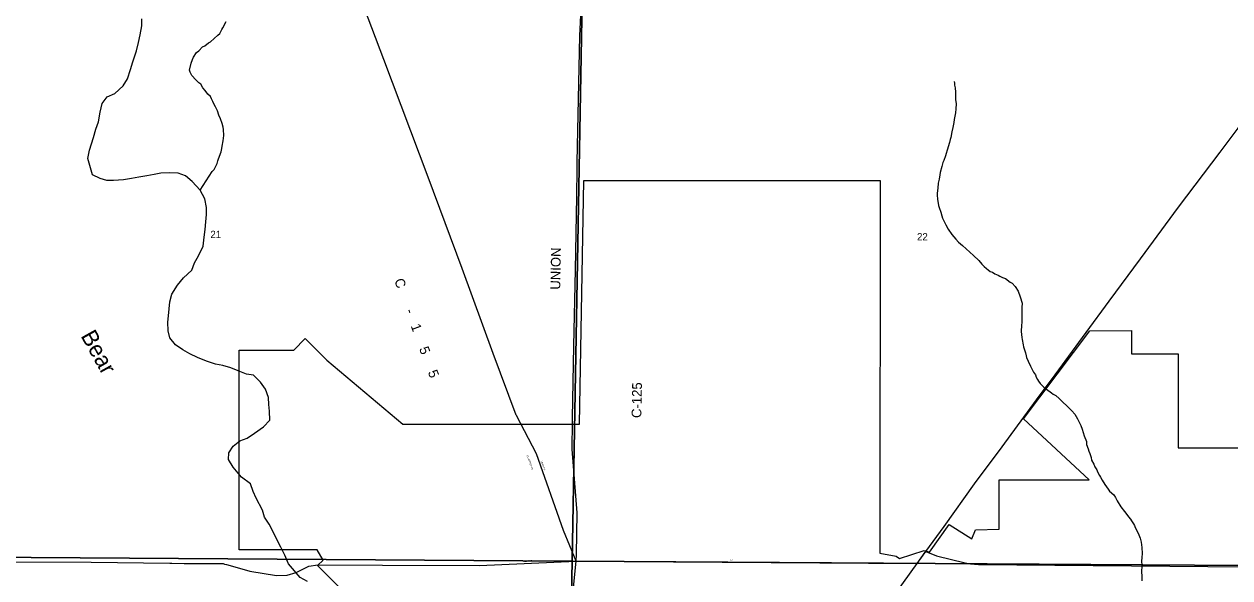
# Model space of a CAD drawing. Extents: x 1312308 to 1684953, y 460642 to 865172.
# Drawn here: x 1455224 to 1464469, y 619650 to 623895 of the extents above; entities that cross this region are included whole.
import ezdxf

# ---------------------------------------------------------------- set-up
doc = ezdxf.new("R2010")
doc.units = 0
for name, color, linetype in [('GM_X_City_Street', 7, 'Continuous'), ('GM_X_City_Street_Text', 7, 'Continuous'), ('GM_X_Corporation', 7, 'Continuous'), ('GM_X_County_Road', 7, 'Continuous'), ('GM_X_County_Road_Text', 7, 'Continuous'), ('GM_X_Minor_River', 7, 'Continuous'), ('GM_X_Minor_River_Text', 7, 'Continuous'), ('GM_X_Section', 7, 'Continuous'), ('GM_X_Section_Text', 7, 'Continuous'), ('GM_X_State_Route', 7, 'Continuous'), ('GM_X_Township_Road', 7, 'Continuous')]:
    doc.layers.add(name, color=color, linetype=linetype)

msp = doc.modelspace()

# ---------------------------------------------------------------- linework, layer by layer
at = {"layer": 'GM_X_City_Street'}
for points in [[(1459457.4, 619777.4), (1459360.2, 620012.5), (1459153.3, 620600.1), (1458999, 620894), (1458997.4, 620898.3)], [(1459458.5, 619829.7), (1459465.2, 620148.8), (1459425.5, 620637.7), (1459429.1, 620847.6), (1459429.6, 620874.9)], [(1456928.7, 619709.6), (1456954.5, 619702.5), (1457158, 619668), (1457240.2, 619672.2), (1457310.8, 619690.7), (1457406, 619738.8), (1457476.4, 619751.3), (1457971.1, 619748.5), (1458714.2, 619746.3), (1459457.4, 619777.4), (1462070.7, 619760.9), (1462136.9, 619851.6), (1462218.3, 619819.8), (1462438.1, 619764.9), (1462481.1, 619757.8), (1462540.7, 619752.3), (1464594.2, 619735.8), (1465504.2, 619732.6), (1466316.9, 619702.8), (1467220.2, 619701.2), (1467975.3, 619702.8)], [(1459363.6, 616687.1), (1459353.3, 616750.7), (1459368.2, 617583), (1459378.8, 618140.6), (1459394.2, 618728.2), (1459401.2, 619217.6), (1459457.4, 619777.4), (1459458.5, 619829.7)], [(1456776.4, 619751.7), (1456928.7, 619709.6)]]:
    msp.add_lwpolyline(points, dxfattribs=at)
at = {"layer": 'GM_X_Corporation'}
msp.add_lwpolyline([(1457716.9, 619501.9), (1457474.3, 619744.7), (1457516.8, 619787.1), (1457471.8, 619865.1), (1456871.8, 619865.2), (1456871.9, 621396.3), (1457290.9, 621396.3), (1457379.3, 621484.7), (1457544, 621319.9), (1458128.5, 620829), (1459482.6, 620828.9), (1459516, 622695.8), (1461786.3, 622695.5), (1461786.2, 619838.6), (1461910.6, 619816.6), (1461935.2, 619799.4), (1462123.8, 619859.7), (1462164.9, 619847.3), (1462315.8, 620058.7), (1462491.3, 619949), (1462519.5, 620019.5), (1462700.8, 620023.4), (1462700.8, 620400.7), (1463390.8, 620400.7), (1462886.2, 620869.4), (1463395.2, 621544.4), (1463713.6, 621547.1), (1463713.6, 621367), (1464073.6, 621367), (1464073.5, 620646.4), (1464703.5, 620646.5)], dxfattribs=at)
at = {"layer": 'GM_X_County_Road'}
for points in [[(1458997.4, 620898.3), (1458819.1, 621371.3), (1458583.5, 622020.5), (1458321, 622722.5), (1457980.8, 623622.7), (1457769.3, 624187), (1457623.6, 624565.4), (1457501.7, 624754.6), (1457352.5, 624890.3), (1457210.6, 624993.7), (1457105.9, 625064), (1457115.4, 625863), (1457105.7, 625964.9), (1457061.5, 626103.5), (1456978.7, 626269), (1456791.8, 626665.5), (1456559.2, 627244.6), (1456374.5, 627669.9), (1456047.3, 628401.2), (1455783.7, 628992)], [(1459463.9, 622759.1), (1459465.3, 622835.9), (1459485.3, 623806.4), (1459520.8, 624537.8), (1459507, 624939.2), (1459508.2, 625062.6)], [(1459461.1, 622602.1), (1459463.9, 622759.1)], [(1459429.6, 620874.9), (1459439.4, 621430), (1459450.6, 622011.6), (1459460.6, 622573.4), (1459461.1, 622602.1)]]:
    msp.add_lwpolyline(points, dxfattribs=at)
at = {"layer": 'GM_X_Minor_River'}
for points in [[(1456622.3, 621311.7), (1456552.7, 621339.8), (1456495.2, 621367.5), (1456441.8, 621399.1), (1456384.5, 621436.9), (1456339.8, 621490.4), (1456329.2, 621545), (1456324.9, 621609.4), (1456330.3, 621659.4), (1456335.8, 621713.5), (1456341.2, 621765.6), (1456356.9, 621825.4), (1456399, 621894.5), (1456446.8, 621949.4), (1456508.6, 622008), (1456530.3, 622065.6), (1456561.9, 622118.9), (1456596.1, 622192.3), (1456604, 622262.4), (1456611.6, 622320.4), (1456617.3, 622380.5), (1456620.8, 622436.7), (1456622.3, 622488.9), (1456610, 622555.5), (1456573.6, 622622.8), (1456513.2, 622688.8), (1456462.1, 622732.4), (1456404.3, 622752.2), (1456336.1, 622754.1), (1456271.7, 622751.9), (1456221.2, 622743.3), (1456164.6, 622730.8), (1456102.1, 622722.5), (1456047.5, 622712), (1455984.9, 622701.7), (1455908.4, 622695.9), (1455858.2, 622695.3), (1455806.3, 622710.8), (1455746.8, 622738.6), (1455726.7, 622811.5), (1455712, 622864.1), (1455725.9, 622930), (1455754.6, 623025.6), (1455772.4, 623089.4), (1455794.1, 623147), (1455806.1, 623219), (1455822, 623286.8), (1455859.6, 623338), (1455918.6, 623362.4), (1455982.5, 623422.9), (1456016.1, 623476.2), (1456038.2, 623547.9), (1456057.8, 623605.6), (1456084.3, 623691.2), (1456100.1, 623755), (1456113.7, 623812.9), (1456125.7, 623882.8), (1456127.1, 623935)], [(1456573.6, 622622.8), (1456665.5, 622766), (1456680, 622779.7), (1456703.3, 622825.4), (1456709.9, 622847.4), (1456714.3, 622863.4), (1456733.8, 622915.2), (1456740.5, 622941.2), (1456743, 622959.3), (1456750.1, 622999.3), (1456755.2, 623041.5), (1456752.3, 623087.8), (1456748.7, 623104), (1456743.4, 623132.3), (1456728.3, 623168.9), (1456716.9, 623197.3), (1456705.7, 623229.8), (1456690.4, 623260.3), (1456678.9, 623284.8), (1456671.4, 623303), (1456659.8, 623323.4), (1456652.2, 623339.7), (1456632.5, 623358.3), (1456611.1, 623387), (1456593.5, 623407.5), (1456578.1, 623434.1), (1456562.3, 623444.5), (1456540.7, 623467.2), (1456509.4, 623502.2), (1456496, 623526.6), (1456492.3, 623540.8), (1456503.8, 623594.8), (1456514.6, 623622.7), (1456523.1, 623640.6), (1456546.2, 623678.3), (1456562.6, 623690), (1456591.6, 623721.4), (1456609.9, 623729), (1456636.6, 623750.5), (1456652.9, 623758.2), (1456708.6, 623811.1), (1456723, 623822.8), (1456739.9, 623852.6), (1456748.3, 623866.5), (1456771.7, 623916.2)], [(1462355.5, 623456.3), (1462357.1, 623442.2), (1462356.7, 623426.1), (1462362.2, 623405.8), (1462365.4, 623373.6), (1462364.9, 623355.5), (1462366.3, 623331.3), (1462366, 623317.2), (1462369.1, 623282.9), (1462368.2, 623246.8), (1462365.3, 623214.6), (1462354, 623164.6), (1462351.3, 623140.5), (1462344.3, 623102.5), (1462337.4, 623070.5), (1462328.2, 623026.4), (1462323.8, 623010.4), (1462319.2, 622986.4), (1462301.6, 622928.5), (1462292.8, 622902.6), (1462288.4, 622886.6), (1462275.4, 622848.7), (1462269, 622834.7), (1462260.1, 622804.8), (1462246.9, 622758.8), (1462244.4, 622740.8), (1462239.5, 622706.7), (1462232.6, 622674.7), (1462229.7, 622638.5), (1462224.6, 622598.4), (1462224.2, 622584.3), (1462227.4, 622552.1), (1462234.3, 622505.6), (1462239.9, 622489.4), (1462253, 622452.9), (1462260.4, 622426.5), (1462266, 622408.3), (1462283.1, 622371.7), (1462290.8, 622357.4), (1462308, 622322.8), (1462337.2, 622281.8), (1462368.5, 622246.8), (1462388, 622224.2), (1462419.5, 622197.3), (1462447.1, 622172.5), (1462474.6, 622147.7), (1462504.1, 622120.8), (1462543.4, 622083.7), (1462566.8, 622054.9), (1462584.4, 622036.4), (1462602.2, 622021.9), (1462616, 622011.5), (1462631.8, 621999), (1462649.7, 621992.5), (1462667.6, 621982.1), (1462691.5, 621971.4), (1462705.3, 621963), (1462725.2, 621952.5), (1462749.1, 621943.9), (1462784.6, 621916.8), (1462798.5, 621908.5), (1462822, 621883.8), (1462845.3, 621849), (1462862.2, 621804.3), (1462875.1, 621755.7), (1462874.2, 621723.5), (1462875, 621675.2), (1462873.3, 621608.9), (1462870.7, 621586.8), (1462869.5, 621538.5), (1462874.3, 621492.1), (1462875.9, 621478), (1462882.9, 621435.6), (1462886.6, 621421.4), (1462901.5, 621374.8), (1462906.9, 621352.5), (1462910.6, 621338.3), (1462922, 621311.9), (1462939.1, 621273.2), (1462962, 621226.4), (1462977.6, 621205.9), (1462983.2, 621187.7), (1462994.8, 621171.3), (1463002.5, 621157), (1463014.2, 621140.6), (1463043.6, 621111.7), (1463063.4, 621097.2), (1463100.8, 621068.1), (1463114.7, 621059.7), (1463134.5, 621047.2), (1463160.1, 621024.4), (1463191.5, 620993.5), (1463217.1, 620972.7), (1463258.3, 620929.5), (1463279.8, 620904.8), (1463301, 620870.1), (1463318.2, 620833.4), (1463325.9, 620819.2), (1463337.2, 620790.7), (1463352, 620738), (1463369, 620695.3)], [(1457396.1, 619622.4), (1457340.7, 619652.1), (1457251.1, 619759.1), (1457222.8, 619824.2), (1457192.3, 619885.3), (1457163.6, 619940.4), (1457133.2, 620003.5), (1457102.7, 620062.6), (1457068, 620115.8), (1457051.3, 620168.5), (1457003.6, 620260.3), (1456978.9, 620313.2), (1456958.4, 620372), (1456889.4, 620422.2), (1456827.2, 620498.3), (1456790.6, 620557.6), (1456794, 620607.7), (1456825.6, 620661.1), (1456876.9, 620701.8), (1456933.8, 620722.3), (1456991.1, 620758.9), (1457058.7, 620809.2), (1457106.4, 620860.1), (1457106.2, 620928.4), (1457099.5, 620978.8), (1457097, 621033.1), (1457074.6, 621096), (1457035.9, 621149.3), (1456983.1, 621205.1), (1456929.1, 621212.6), (1456865.4, 621236.5), (1456809.8, 621260.2), (1456746, 621278.1), (1456692, 621289.6), (1456622.3, 621311.7)], [(1463369, 620695.3), (1463370.4, 620673.2), (1463381.6, 620638.7), (1463387.2, 620620.5), (1463394.8, 620604.2), (1463404.1, 620573.8), (1463407.6, 620553.5), (1463424.8, 620520.9), (1463432.4, 620502.6), (1463447.9, 620478.1), (1463453.5, 620461.9), (1463468.9, 620435.3), (1463476.6, 620421.1), (1463490.1, 620398.6), (1463511.4, 620365.9), (1463536.7, 620331.1), (1463546.3, 620314.7), (1463579.8, 620285.8), (1463591.3, 620265.3), (1463604.8, 620240.9), (1463633.8, 620195.9), (1463661, 620159), (1463678.6, 620136.4), (1463692.2, 620118), (1463707.9, 620101.5), (1463713.5, 620087.3), (1463731.1, 620064.7), (1463738.7, 620050.5), (1463742.4, 620036.3), (1463754, 620017.9), (1463771.1, 619979.2), (1463780.5, 619954.9), (1463787.8, 619924.5), (1463794.8, 619882.1), (1463795.6, 619837.8), (1463794.8, 619805.6), (1463792.1, 619779.5), (1463793.3, 619747.3), (1463791.8, 619691), (1463793.3, 619668.8), (1463792.8, 619650.7), (1463794.2, 619628.5)]]:
    msp.add_lwpolyline(points, dxfattribs=at)
at = {"layer": 'GM_X_Section'}
for points in [[(1454204, 625082.2), (1459521.5, 625085.3), (1459424.8, 619777.8), (1454142, 619813.9)], [(1459521.5, 625085.3), (1464682.6, 625067.6), (1464595.6, 619745.9), (1459424.8, 619777.8)], [(1453924, 619812.3), (1454142, 619813.9), (1459424.8, 619777.8), (1459323.4, 614534.3), (1453806.8, 614577.1)], [(1459424.8, 619777.8), (1464595.6, 619745.9), (1464555.5, 614469.2), (1459323.4, 614534.3)]]:
    msp.add_lwpolyline(points, close=True, dxfattribs=at)
at = {"layer": 'GM_X_State_Route'}
for points in [[(1462133.4, 619846.8), (1462136.9, 619851.6), (1462277.5, 620045.1), (1462510.9, 620371.2), (1462722.4, 620655.1), (1462985.7, 621014.4), (1463128.5, 621207.8), (1463365.9, 621530.7), (1463544.4, 621771), (1463782.5, 622095.3), (1464076.3, 622490.6), (1464395.5, 622913.6), (1464533.8, 623096.7), (1464655.1, 623272.2)], [(1461211.4, 618589.9), (1461346.1, 618770.7), (1461604.2, 619122.6), (1461848.3, 619452.1), (1462070.7, 619760.9), (1462133.4, 619846.8)]]:
    msp.add_lwpolyline(points, dxfattribs=at)
at = {"layer": 'GM_X_Township_Road'}
for points in [[(1454144, 619786), (1454928.9, 619772.8), (1455738.2, 619771.2), (1456341, 619763.1), (1456356, 619762.9)], [(1456356, 619762.9), (1456451, 619761.7), (1456749.4, 619759.2), (1456759.7, 619756.3), (1456776.4, 619751.7)]]:
    msp.add_lwpolyline(points, dxfattribs=at)

# ---------------------------------------------------------------- texts
at = {"layer": 'GM_X_City_Street_Text'}
for s, rotation, p in [('ELLERTON RD', 289.72894, (1459076.3, 620587.9)), ('LIBERTY-', 289.59279, (1459184.2, 620545.2)), ('HEMPLE', 2.04429, (1459047.4, 619772)), ('RD', 0.00001, (1460631.7, 619780.8))]:
    msp.add_text(s, height=12.5, rotation=rotation, dxfattribs=at).set_placement(p)
at = {"layer": 'GM_X_County_Road_Text'}
for s, rotation, p in [('UNION', 89.15192, (1459334.4, 621859.1)), ('C', 289.9631, (1458060.6, 621930.5)), ('-', 289.97672, (1458144.7, 621698.9)), ('1', 290.08011, (1458187, 621582.5)), ('5', 290.38085, (1458251.1, 621407.3)), ('5', 291.68667, (1458318.1, 621227.1)), ('C-125', 88.89784, (1459956, 620875.2))]:
    msp.add_text(s, height=75, rotation=rotation, dxfattribs=at).set_placement(p)
at = {"layer": 'GM_X_Minor_River_Text'}
msp.add_text('Bear', height=125.08, rotation=299.16531, dxfattribs=at).set_placement((1455654.5, 621505.7))
at = {"layer": 'GM_X_Section_Text'}
for s, p in [('21', (1456651.9, 622255.6)), ('22', (1462070.5, 622238))]:
    msp.add_text(s, height=55.25, rotation=0.00001, dxfattribs=at).set_placement(p)

doc.saveas('drawing.dxf')
